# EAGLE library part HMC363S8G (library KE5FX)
HBT STATIC DIVIDER, DC - 12.0 GHz, DIVIDE BY 8 Source: http://www.hittite.com/product_info/product_specs/dividersdetectors/hmc363s8g.pdf
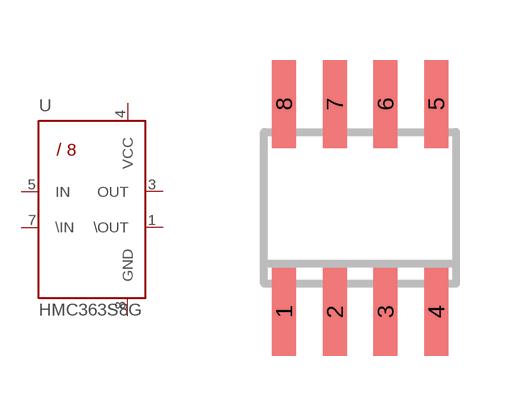
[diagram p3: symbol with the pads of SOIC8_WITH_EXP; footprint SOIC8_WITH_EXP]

Designator prefix U

## HMC363S8G  [SOIC8_WITH_EXP]
1  \OUT  out
3  OUT  out
4  VCC  pwr
5  IN  in
7  \IN  in
8  GND  pwr

## Footprint SOIC8_WITH_EXP (pad centres in mm)
smd 0.6 x 2.2: 1 -6.35,-0.06; 2 -5.08,-0.06; 3 -3.81,-0.06; 4 -2.54,-0.06; 5 -2.54,5.14; 6 -3.81,5.14; 7 -5.08,5.14; 8 -6.35,5.14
